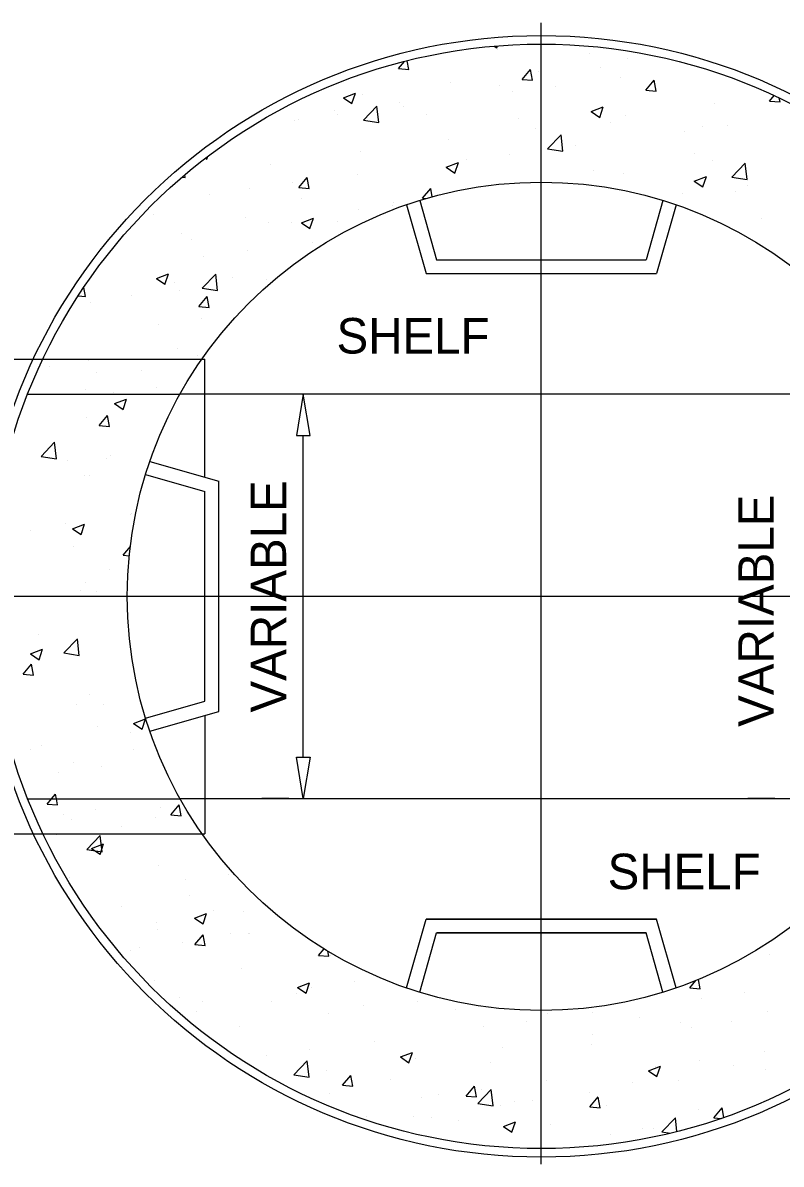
# Model space of a CAD drawing. Extents: x 6712067 to 6713867, y 1867712 to 1869162.
# Drawn here: x 6712215.7 to 6712343.8, y 1867926.2 to 1868119 of the extents above; entities that cross this region are included whole.
import ezdxf

# ---------------------------------------------------------------- set-up
doc = ezdxf.new("R2010")
doc.units = 0
for name, color, linetype in [('G-MARK', 7, 'Continuous'), ('G-TEXT', 7, 'Continuous'), ('Misc CnstDet(22)', 7, 'Continuous')]:
    doc.layers.add(name, color=color, linetype=linetype)

msp = doc.modelspace()

# ---------------------------------------------------------------- linework, layer by layer
at = {"layer": 'G-MARK'}
msp.add_line((6712263.06, 1867994.97), (6712263.06, 1868049.33), dxfattribs=at)
at = {"layer": 'G-TEXT'}
for points in [[(6712261.9, 1868049.33), (6712264.23, 1868049.33), (6712263.06, 1868056.33)], [(6712261.9, 1867994.97), (6712264.23, 1867994.97), (6712263.06, 1867987.98)]]:
    msp.add_lwpolyline(points, close=True, dxfattribs=at)
at = {"layer": 'Misc CnstDet(22)'}
for p, q in [((6712303.29, 1867926.23), (6712303.29, 1868119.03)), ((6712295.35, 1868115.08), (6712295.78, 1868114.8)), ((6712295.78, 1868114.8), (6712295.9, 1868115.13)), ((6712295.88, 1868114.46), (6712295.88, 1868114.46)), ((6712279.15, 1868111.31), (6712280.16, 1868112.51)), ((6712280.9, 1868111.16), (6712280.62, 1868112.63)), ((6712311.44, 1868113.81), (6712311.44, 1868113.81)), ((6712317.89, 1868113.05), (6712317.89, 1868113.05)), ((6712279.15, 1868111.31), (6712280.9, 1868111.16)), ((6712300.06, 1868109.48), (6712301.48, 1868111.16)), ((6712301.81, 1868109.32), (6712301.46, 1868111.16)), ((6712302.75, 1868110.86), (6712302.75, 1868110.86)), ((6712313.3, 1868111.42), (6712313.3, 1868111.42)), ((6712288.03, 1868109), (6712288.03, 1868109)), ((6712296.3, 1868108.51), (6712296.3, 1868108.51)), ((6712300.06, 1868109.48), (6712301.81, 1868109.33)), ((6712305.65, 1868108.33), (6712305.65, 1868108.33)), ((6712316.69, 1868109.78), (6712316.69, 1868109.78)), ((6712320.97, 1868107.65), (6712322.37, 1868109.32)), ((6712322.72, 1868107.5), (6712322.37, 1868109.32)), ((6712269.84, 1868106.37), (6712271.88, 1868107.15)), ((6712269.84, 1868106.37), (6712271.29, 1868105.4)), ((6712271.29, 1868105.4), (6712271.88, 1868107.15)), ((6712273.06, 1868106.95), (6712273.06, 1868106.95)), ((6712298.37, 1868107.37), (6712298.37, 1868107.37)), ((6712320.97, 1868107.65), (6712322.72, 1868107.5)), ((6712341.88, 1868105.82), (6712342.64, 1868106.73)), ((6712343.63, 1868105.67), (6712343.5, 1868106.31)), ((6712273.26, 1868102.6), (6712275.52, 1868104.96)), ((6712275.84, 1868102.18), (6712275.52, 1868104.96)), ((6712279.3, 1868105.58), (6712279.3, 1868105.58)), ((6712279.95, 1868104.95), (6712279.95, 1868104.95)), ((6712311.74, 1868104.04), (6712313.77, 1868104.82)), ((6712313.18, 1868103.06), (6712313.77, 1868104.82)), ((6712332.5, 1868105.4), (6712332.5, 1868105.4)), ((6712341.88, 1868105.82), (6712343.63, 1868105.67)), ((6712261.62, 1868102.54), (6712261.62, 1868102.54)), ((6712262.3, 1868102.66), (6712262.3, 1868102.66)), ((6712268.37, 1868104.23), (6712268.37, 1868104.23)), ((6712268.91, 1868103.49), (6712268.91, 1868103.49)), ((6712273.26, 1868102.6), (6712275.84, 1868102.19)), ((6712283.93, 1868103.56), (6712283.93, 1868103.56)), ((6712299.49, 1868102.91), (6712299.49, 1868102.91)), ((6712311.74, 1868104.04), (6712313.18, 1868103.06)), ((6712317.53, 1868103.34), (6712317.53, 1868103.34)), ((6712302.39, 1868101.16), (6712302.39, 1868101.16)), ((6712315.05, 1868102.25), (6712315.05, 1868102.25)), ((6712327.43, 1868100.71), (6712327.43, 1868100.71)), ((6712330.61, 1868101.6), (6712330.61, 1868101.6)), ((6712334.73, 1868101.68), (6712334.73, 1868101.68)), ((6712287.67, 1868099.29), (6712287.67, 1868099.29)), ((6712304.36, 1868097.76), (6712306.63, 1868100.13)), ((6712306.95, 1868097.36), (6712306.63, 1868100.13)), ((6712272.71, 1868097.24), (6712272.71, 1868097.24)), ((6712297.99, 1868096.84), (6712297.99, 1868096.84)), ((6712304.36, 1868097.76), (6712306.95, 1868097.36)), ((6712309.03, 1868098.29), (6712309.03, 1868098.29)), ((6712329.1, 1868096.95), (6712329.1, 1868096.95)), ((6712246.54, 1868096.17), (6712246.8, 1868096)), ((6712246.79, 1868095.99), (6712246.96, 1868096.5)), ((6712257.56, 1868095.06), (6712257.56, 1868095.06)), ((6712287.23, 1868094.63), (6712289.28, 1868095.42)), ((6712288.69, 1868093.66), (6712289.28, 1868095.41)), ((6712290.69, 1868095.87), (6712290.69, 1868095.87)), ((6712332.14, 1868095.7), (6712332.14, 1868095.7)), ((6712335.47, 1868092.94), (6712337.74, 1868095.31)), ((6712338.06, 1868092.54), (6712337.74, 1868095.31)), ((6712242.56, 1868092.94), (6712243.13, 1868092.89)), ((6712243.13, 1868092.89), (6712243.04, 1868093.36)), ((6712262.3, 1868091.21), (6712263.7, 1868092.89)), ((6712264.04, 1868091.06), (6712263.7, 1868092.89)), ((6712272.28, 1868093.45), (6712272.28, 1868093.45)), ((6712287.23, 1868094.63), (6712288.69, 1868093.66)), ((6712312.09, 1868094.02), (6712312.09, 1868094.02)), ((6712317.17, 1868093.64), (6712317.17, 1868093.64)), ((6712329.13, 1868092.3), (6712331.18, 1868093.08)), ((6712330.58, 1868091.33), (6712331.18, 1868093.08)), ((6712335.47, 1868092.94), (6712338.06, 1868092.54)), ((6712253.94, 1868091.04), (6712253.94, 1868091.04)), ((6712261.24, 1868091.99), (6712261.24, 1868091.99)), ((6712262.3, 1868091.21), (6712264.04, 1868091.06)), ((6712283.21, 1868089.39), (6712284.61, 1868091.06)), ((6712284.87, 1868089.64), (6712284.61, 1868091.05)), ((6712329.13, 1868092.3), (6712330.58, 1868091.33)), ((6712338.11, 1868091.63), (6712338.11, 1868091.63)), ((6712247.14, 1868089.98), (6712247.14, 1868089.98)), ((6712262.7, 1868089.33), (6712262.7, 1868089.33)), ((6712282.74, 1868089.02), (6712285.59, 1868078.99)), ((6712283.21, 1868089.39), (6712283.79, 1868089.33)), ((6712323.85, 1868089.02), (6712321, 1868078.99)), ((6712327.07, 1868090.18), (6712327.07, 1868090.18)), ((6712336.08, 1868090.55), (6712336.08, 1868090.55)), ((6712272.35, 1868087.54), (6712272.35, 1868087.54)), ((6712278.1, 1868088.19), (6712278.1, 1868088.19)), ((6712278.26, 1868088.66), (6712278.26, 1868088.66)), ((6712280.51, 1868088.3), (6712283.84, 1868076.66)), ((6712326.08, 1868088.3), (6712322.75, 1868076.66)), ((6712237.72, 1868086.72), (6712237.72, 1868086.72)), ((6712253.28, 1868086.07), (6712253.28, 1868086.07)), ((6712257.21, 1868085.35), (6712257.21, 1868085.35)), ((6712261.09, 1868085.28), (6712261.09, 1868085.28)), ((6712262.74, 1868085.23), (6712264.79, 1868086.01)), ((6712262.74, 1868085.23), (6712264.2, 1868084.26)), ((6712264.2, 1868084.26), (6712264.79, 1868086.01)), ((6712268.84, 1868085.42), (6712268.84, 1868085.42)), ((6712340.49, 1868086.04), (6712340.49, 1868086.04)), ((6712242.49, 1868083.49), (6712242.49, 1868083.49)), ((6712244.1, 1868082.35), (6712244.1, 1868082.35)), ((6712264.61, 1868081.95), (6712264.61, 1868081.95)), ((6712246.28, 1868079.54), (6712246.28, 1868079.54)), ((6712253.57, 1868080.5), (6712253.57, 1868080.5)), ((6712285.59, 1868078.99), (6712321, 1868078.99)), ((6712238.25, 1868075.83), (6712240.3, 1868076.61)), ((6712238.25, 1868075.83), (6712239.7, 1868074.86)), ((6712239.7, 1868074.85), (6712240.3, 1868076.61)), ((6712246.01, 1868074.19), (6712248.27, 1868076.57)), ((6712248.59, 1868073.79), (6712248.27, 1868076.56)), ((6712251.08, 1868075.96), (6712251.08, 1868075.96)), ((6712256.86, 1868075.65), (6712256.86, 1868075.65)), ((6712283.84, 1868076.66), (6712322.75, 1868076.66)), ((6712226.26, 1868072.79), (6712225.99, 1868074.33)), ((6712241.34, 1868075.17), (6712241.34, 1868075.17)), ((6712242.13, 1868073.78), (6712242.13, 1868073.78)), ((6712246.01, 1868074.19), (6712248.59, 1868073.79)), ((6712256.89, 1868074.51), (6712256.89, 1868074.51)), ((6712225.03, 1868072.9), (6712226.26, 1868072.79)), ((6712227.17, 1868071.73), (6712227.17, 1868071.73)), ((6712234.08, 1868073.03), (6712234.08, 1868073.03)), ((6712245.43, 1868071.12), (6712246.84, 1868072.79)), ((6712247.17, 1868070.96), (6712246.84, 1868072.79)), ((6712245.43, 1868071.12), (6712247.17, 1868070.97)), ((6712238.61, 1868068.04), (6712238.61, 1868068.04)), ((6712245.91, 1868069.01), (6712245.91, 1868069.01)), ((6712241.78, 1868064.08), (6712241.78, 1868064.08)), ((6712189.47, 1868062.22), (6712217.46, 1868062.22)), ((6712217.46, 1868062.22), (6712246.46, 1868062.22)), ((6712226.81, 1868062.03), (6712226.81, 1868062.03)), ((6712245.22, 1868062.84), (6712245.22, 1868062.84)), ((6712246.46, 1868042.27), (6712246.46, 1868062.22)), ((6712220.1, 1868060.93), (6712220.1, 1868060.93)), ((6712235.66, 1868060.27), (6712235.66, 1868060.27)), ((6712228.21, 1868059.92), (6712228.21, 1868059.92)), ((6712216.51, 1868056.32), (6712242.25, 1868056.32)), ((6712226.25, 1868057.01), (6712226.25, 1868057.01)), ((6712230.94, 1868056.54), (6712230.94, 1868056.54)), ((6712238.24, 1868057.51), (6712238.24, 1868057.51)), ((6712241.8, 1868056.36), (6712241.8, 1868056.36)), ((6712364.34, 1868056.32), (6712242.25, 1868056.32)), ((6712260.62, 1868056.33), (6712256.07, 1868056.33)), ((6712263.06, 1868056.33), (6712263.06, 1868056.33)), ((6712263.06, 1868056.33), (6712263.06, 1868056.33)), ((6712342.74, 1868056.33), (6712338.2, 1868056.33)), ((6712231.16, 1868054.7), (6712233.2, 1868055.48)), ((6712231.16, 1868054.7), (6712232.61, 1868053.72)), ((6712232.61, 1868053.72), (6712233.2, 1868055.48)), ((6712226.46, 1868052.32), (6712226.46, 1868052.32)), ((6712228.57, 1868051.02), (6712229.97, 1868052.7)), ((6712230.31, 1868050.86), (6712229.97, 1868052.69)), ((6712228.57, 1868051.02), (6712230.31, 1868050.86)), ((6712218.76, 1868045.8), (6712221.03, 1868048.17)), ((6712221.35, 1868045.4), (6712221.03, 1868048.17)), ((6712218.76, 1868045.8), (6712221.35, 1868045.4)), ((6712223.28, 1868045.06), (6712223.28, 1868045.06)), ((6712229.87, 1868045.46), (6712229.87, 1868045.46)), ((6712230.57, 1868046.01), (6712230.57, 1868046.01)), ((6712237.15, 1868044.93), (6712248.79, 1868041.6)), ((6712226.1, 1868042.62), (6712226.1, 1868042.62)), ((6712236.43, 1868042.71), (6712246.46, 1868039.85)), ((6712227.01, 1868042.53), (6712227.01, 1868042.53)), ((6712248.79, 1868002.69), (6712248.79, 1868041.6)), ((6712246.46, 1868004.45), (6712246.46, 1868039.85)), ((6712233.94, 1868035.97), (6712233.94, 1868035.97)), ((6712234, 1868036.13), (6712234, 1868036.13)), ((6712217, 1868033.21), (6712217, 1868033.21)), ((6712222.9, 1868034.51), (6712222.9, 1868034.51)), ((6712224.07, 1868033.56), (6712226.11, 1868034.34)), ((6712224.07, 1868033.56), (6712225.52, 1868032.58)), ((6712225.52, 1868032.58), (6712226.11, 1868034.34)), ((6712225.75, 1868032.91), (6712225.75, 1868032.91)), ((6712224.18, 1868030.56), (6712224.18, 1868030.56)), ((6712232.61, 1868029.09), (6712233.85, 1868030.56)), ((6712232.61, 1868029.09), (6712233.68, 1868029)), ((6712230.32, 1868026.65), (6712230.32, 1868026.65)), ((6712226.27, 1868024.47), (6712226.27, 1868024.47)), ((6712421.49, 1868022.15), (6712182.32, 1868022.15)), ((6712225.39, 1868023.22), (6712225.39, 1868023.22)), ((6712228.13, 1868023.01), (6712228.13, 1868023.01)), ((6712218.39, 1868015.75), (6712218.39, 1868015.75)), ((6712222.62, 1868012.58), (6712224.9, 1868014.95)), ((6712225.22, 1868012.18), (6712224.9, 1868014.94)), ((6712216.98, 1868012.42), (6712219.02, 1868013.21)), ((6712216.98, 1868012.42), (6712218.42, 1868011.44)), ((6712218.42, 1868011.44), (6712219.02, 1868013.2)), ((6712218.61, 1868012.97), (6712218.61, 1868012.97)), ((6712222.62, 1868012.58), (6712225.22, 1868012.18)), ((6712225.03, 1868013.51), (6712225.03, 1868013.51)), ((6712215.75, 1868009), (6712217.15, 1868010.67)), ((6712217.49, 1868008.84), (6712217.15, 1868010.67)), ((6712215.75, 1868009), (6712217.49, 1868008.85)), ((6712226.93, 1868005.61), (6712226.93, 1868005.61)), ((6712236.43, 1868001.58), (6712246.46, 1868004.45)), ((6712224.68, 1868003.81), (6712224.68, 1868003.81)), ((6712229.35, 1868003.9), (6712229.35, 1868003.9)), ((6712237.15, 1867999.37), (6712248.79, 1868002.69)), ((6712234.38, 1868000.69), (6712236.42, 1868001.47)), ((6712234.38, 1868000.69), (6712235.83, 1867999.7)), ((6712235.82, 1867999.7), (6712236.42, 1868001.47)), ((6712246.46, 1868002.02), (6712246.46, 1867982.06)), ((6712228.27, 1868000.2), (6712228.27, 1868000.2)), ((6712233.92, 1867999.22), (6712233.92, 1867999.22)), ((6712218.86, 1867996.94), (6712218.86, 1867996.94)), ((6712216.91, 1867996.29), (6712216.91, 1867996.29)), ((6712234.41, 1867996.27), (6712234.41, 1867996.27)), ((6712224.32, 1867994.1), (6712224.32, 1867994.1)), ((6712228.97, 1867993.37), (6712228.97, 1867993.37)), ((6712221.68, 1867992.4), (6712221.68, 1867992.4)), ((6712220.55, 1867987.97), (6712221.2, 1867988.74)), ((6712221.34, 1867987.97), (6712221.2, 1867988.74)), ((6712216.51, 1867987.97), (6712242.25, 1867987.97)), ((6712219.79, 1867987.07), (6712220.55, 1867987.97)), ((6712219.79, 1867987.07), (6712221.53, 1867986.92)), ((6712221.53, 1867986.92), (6712221.34, 1867987.97)), ((6712240.7, 1867985.24), (6712242.11, 1867986.92)), ((6712242.44, 1867985.08), (6712242.11, 1867986.92)), ((6712364.34, 1867987.97), (6712242.25, 1867987.97)), ((6712260.62, 1867987.98), (6712256.07, 1867987.98)), ((6712263.06, 1867987.98), (6712263.06, 1867987.98)), ((6712342.74, 1867987.98), (6712338.2, 1867987.98)), ((6712222.47, 1867985.38), (6712222.47, 1867985.38)), ((6712228.04, 1867986.1), (6712228.04, 1867986.1)), ((6712238.94, 1867986.45), (6712238.94, 1867986.45)), ((6712240.7, 1867985.24), (6712242.44, 1867985.09)), ((6712223.98, 1867984.4), (6712223.98, 1867984.4)), ((6712232.34, 1867983.33), (6712232.34, 1867983.33)), ((6712238.02, 1867984.71), (6712238.02, 1867984.71)), ((6712189.47, 1867982.06), (6712217.46, 1867982.06)), ((6712217.46, 1867982.06), (6712246.46, 1867982.06)), ((6712221.3, 1867981.87), (6712221.3, 1867981.87)), ((6712226.49, 1867979.37), (6712228.76, 1867981.73)), ((6712229.09, 1867978.97), (6712228.76, 1867981.73)), ((6712226.49, 1867979.37), (6712229.09, 1867978.97)), ((6712227.28, 1867979.55), (6712229.33, 1867980.33)), ((6712227.28, 1867979.55), (6712228.74, 1867978.57)), ((6712228.73, 1867978.56), (6712229.33, 1867980.33)), ((6712238.59, 1867976.75), (6712238.59, 1867976.75)), ((6712250.38, 1867975.21), (6712250.38, 1867975.21)), ((6712223.62, 1867974.7), (6712223.62, 1867974.7)), ((6712243.09, 1867974.25), (6712243.09, 1867974.25)), ((6712243.84, 1867971.62), (6712243.84, 1867971.62)), ((6712232.36, 1867969.82), (6712232.36, 1867969.82)), ((6712244.68, 1867967.81), (6712246.72, 1867968.59)), ((6712244.68, 1867967.81), (6712246.14, 1867966.84)), ((6712246.14, 1867966.84), (6712246.72, 1867968.59)), ((6712247.92, 1867969.16), (6712247.92, 1867969.16)), ((6712252.96, 1867968.91), (6712252.96, 1867968.91)), ((6712280.51, 1867956), (6712283.84, 1867967.64)), ((6712280.51, 1867956), (6712283.84, 1867967.64)), ((6712283.84, 1867967.64), (6712322.75, 1867967.64)), ((6712322.75, 1867967.64), (6712283.84, 1867967.64)), ((6712326.08, 1867956), (6712322.75, 1867967.64)), ((6712326.08, 1867956), (6712322.75, 1867967.64)), ((6712238.23, 1867967.04), (6712238.23, 1867967.04)), ((6712238.5, 1867965.91), (6712238.5, 1867965.91)), ((6712242.72, 1867963.71), (6712242.72, 1867963.71)), ((6712244.75, 1867963.31), (6712246.15, 1867964.99)), ((6712246.48, 1867963.16), (6712246.15, 1867964.99)), ((6712250.82, 1867965.23), (6712250.82, 1867965.23)), ((6712253.76, 1867965.17), (6712253.76, 1867965.17)), ((6712254.06, 1867965.25), (6712254.06, 1867965.25)), ((6712282.74, 1867955.28), (6712285.59, 1867965.31)), ((6712282.74, 1867955.28), (6712285.59, 1867965.31)), ((6712285.59, 1867965.31), (6712321, 1867965.31)), ((6712321, 1867965.31), (6712285.59, 1867965.31)), ((6712323.85, 1867955.28), (6712321, 1867965.31)), ((6712323.85, 1867955.28), (6712321, 1867965.31)), ((6712233.82, 1867962.3), (6712233.82, 1867962.3)), ((6712235.42, 1867962.75), (6712235.42, 1867962.75)), ((6712244.75, 1867963.31), (6712246.49, 1867963.16)), ((6712265.66, 1867961.49), (6712266.59, 1867962.6)), ((6712267.39, 1867961.34), (6712267.23, 1867962.2)), ((6712341.91, 1867961.72), (6712341.91, 1867961.72)), ((6712265.66, 1867961.49), (6712267.39, 1867961.34)), ((6712267.74, 1867961.4), (6712267.74, 1867961.4)), ((6712252.6, 1867959.2), (6712252.6, 1867959.2)), ((6712237.88, 1867957.34), (6712237.88, 1867957.34)), ((6712262.08, 1867956.07), (6712264.12, 1867956.86)), ((6712262.08, 1867956.07), (6712263.54, 1867955.1)), ((6712263.54, 1867955.1), (6712264.12, 1867956.85)), ((6712264.5, 1867956.09), (6712264.5, 1867956.09)), ((6712271.8, 1867957.06), (6712271.8, 1867957.06)), ((6712328.38, 1867956), (6712329.43, 1867957.25)), ((6712328.38, 1867956), (6712330.12, 1867955.85)), ((6712330.12, 1867955.84), (6712329.83, 1867957.41)), ((6712242.11, 1867954.35), (6712242.11, 1867954.35)), ((6712261.95, 1867955.03), (6712261.95, 1867955.03)), ((6712330.33, 1867954.27), (6712330.33, 1867954.27)), ((6712337.61, 1867955.23), (6712337.61, 1867955.23)), ((6712244.96, 1867952.1), (6712244.96, 1867952.1)), ((6712246.09, 1867953.67), (6712246.09, 1867953.67)), ((6712257.67, 1867953.7), (6712257.67, 1867953.7)), ((6712273.23, 1867953.03), (6712273.23, 1867953.03)), ((6712282.35, 1867953.74), (6712282.35, 1867953.74)), ((6712288.79, 1867952.38), (6712288.79, 1867952.38)), ((6712341.55, 1867952.01), (6712341.55, 1867952.01)), ((6712267.38, 1867951.69), (6712267.38, 1867951.69)), ((6712300.87, 1867950.39), (6712300.87, 1867950.39)), ((6712304.36, 1867951.72), (6712304.36, 1867951.72)), ((6712311.91, 1867951.85), (6712311.91, 1867951.85)), ((6712319.92, 1867951.06), (6712319.92, 1867951.06)), ((6712326.83, 1867950.14), (6712326.83, 1867950.14)), ((6712335.48, 1867950.4), (6712335.48, 1867950.4)), ((6712252.24, 1867949.51), (6712252.24, 1867949.51)), ((6712293.58, 1867949.44), (6712293.58, 1867949.44)), ((6712328.75, 1867949.3), (6712328.75, 1867949.3)), ((6712275.16, 1867947), (6712275.16, 1867947)), ((6712311.75, 1867946.38), (6712311.75, 1867946.38)), ((6712311.86, 1867948.09), (6712311.86, 1867948.09)), ((6712256.83, 1867944.59), (6712256.83, 1867944.59)), ((6712264.12, 1867945.56), (6712264.12, 1867945.56)), ((6712279.49, 1867944.34), (6712281.52, 1867945.12)), ((6712279.49, 1867944.34), (6712280.93, 1867943.37)), ((6712280.93, 1867943.36), (6712281.52, 1867945.12)), ((6712296.72, 1867945.9), (6712296.72, 1867945.9)), ((6712340.99, 1867945.19), (6712340.99, 1867945.19)), ((6712261.47, 1867941.32), (6712263.73, 1867943.69)), ((6712264.05, 1867940.91), (6712263.73, 1867943.69)), ((6712282, 1867944.03), (6712282, 1867944.03)), ((6712294.75, 1867943.47), (6712294.75, 1867943.47)), ((6712321.38, 1867942), (6712323.42, 1867942.79)), ((6712322.65, 1867942.77), (6712322.65, 1867942.77)), ((6712322.82, 1867941.03), (6712323.42, 1867942.78)), ((6712329.95, 1867943.73), (6712329.95, 1867943.73)), ((6712335.73, 1867942.91), (6712335.73, 1867942.91)), ((6712261.47, 1867941.32), (6712264.05, 1867940.92)), ((6712267.02, 1867941.99), (6712267.02, 1867941.99)), ((6712269.7, 1867939.56), (6712271.1, 1867941.23)), ((6712271.44, 1867939.41), (6712271.1, 1867941.23)), ((6712277.75, 1867940.54), (6712277.75, 1867940.54)), ((6712321.38, 1867942), (6712322.82, 1867941.03)), ((6712326.47, 1867940.44), (6712326.47, 1867940.44)), ((6712341.19, 1867942.3), (6712341.19, 1867942.3)), ((6712269.7, 1867939.56), (6712271.44, 1867939.41)), ((6712290.61, 1867937.73), (6712292.01, 1867939.41)), ((6712292.35, 1867937.58), (6712292.01, 1867939.41)), ((6712292.57, 1867936.49), (6712294.84, 1867938.86)), ((6712293.2, 1867938.9), (6712293.2, 1867938.9)), ((6712295.16, 1867936.09), (6712294.84, 1867938.86)), ((6712304.24, 1867940.35), (6712304.24, 1867940.35)), ((6712318.74, 1867939.98), (6712318.74, 1867939.98)), ((6712267.56, 1867938.13), (6712267.56, 1867938.13)), ((6712283.11, 1867937.48), (6712283.11, 1867937.48)), ((6712285.9, 1867937.94), (6712285.9, 1867937.94)), ((6712290.61, 1867937.73), (6712292.35, 1867937.58)), ((6712298.68, 1867936.83), (6712298.68, 1867936.83)), ((6712301.74, 1867937.07), (6712301.74, 1867937.07)), ((6712311.51, 1867938.39), (6712311.51, 1867938.39)), ((6712311.52, 1867935.91), (6712312.92, 1867937.58)), ((6712313.25, 1867935.75), (6712312.92, 1867937.57)), ((6712292.57, 1867936.49), (6712295.16, 1867936.09)), ((6712296.37, 1867936.21), (6712296.37, 1867936.21)), ((6712311.52, 1867935.91), (6712313.26, 1867935.75)), ((6712314.24, 1867936.17), (6712314.24, 1867936.17)), ((6712329.8, 1867935.51), (6712329.8, 1867935.51)), ((6712332.43, 1867934.07), (6712333.83, 1867935.75)), ((6712334.12, 1867934.12), (6712333.83, 1867935.75)), ((6712273.7, 1867934.22), (6712273.7, 1867934.22)), ((6712281.65, 1867934.33), (6712281.65, 1867934.33)), ((6712284.73, 1867934.15), (6712284.73, 1867934.15)), ((6712289.27, 1867933.57), (6712289.27, 1867933.57)), ((6712296.89, 1867932.6), (6712298.93, 1867933.38)), ((6712298.33, 1867931.63), (6712298.93, 1867933.38)), ((6712304.83, 1867932.91), (6712304.83, 1867932.91)), ((6712323.68, 1867931.67), (6712325.95, 1867934.04)), ((6712326.22, 1867931.73), (6712325.95, 1867934.04)), ((6712332.43, 1867934.07), (6712333.69, 1867933.97)), ((6712296.89, 1867932.6), (6712298.33, 1867931.63)), ((6712314.98, 1867931.28), (6712314.98, 1867931.28)), ((6712320.39, 1867932.25), (6712320.39, 1867932.25)), ((6712322.28, 1867932.23), (6712322.28, 1867932.23)), ((6712323.68, 1867931.67), (6712325.08, 1867931.45))]:
    msp.add_line(p, q, dxfattribs=at)
for radius in [94.73, 93.28, 69.96]:
    msp.add_circle((6712303.29, 1868022.15), radius, dxfattribs=at)

# ---------------------------------------------------------------- texts
for p in [(6712268.69, 1868063.17), (6712314.5, 1867972.68)]:
    msp.add_text('SHELF', height=6, dxfattribs=at).set_placement(p)
for p in [(6712260.18, 1868002.52), (6712342.58, 1868000.1)]:
    msp.add_text('VARIABLE', height=6, rotation=90, dxfattribs=at).set_placement(p)

doc.saveas('drawing.dxf')
